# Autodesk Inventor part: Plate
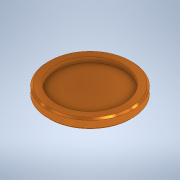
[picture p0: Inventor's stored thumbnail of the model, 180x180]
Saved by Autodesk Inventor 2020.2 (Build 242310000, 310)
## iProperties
Created: 2020-01
Part Number: Plate
Material: Gold
Document SubType Name: Modeling
Designer: thira
Density: 19.3 g/cm^3
Appearance: Metal 1600F Hot
Author: thira
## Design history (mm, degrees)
sketch "Sketch1"
  geometry: C1 r 125 at (0, 0); C2 r 100 at (0, 0); 1 further point
  constraints: 2 centre point, 2 coincident
  dimensions: "d0" = 250 diameter of C1; "d1" = 200 diameter of C2
extrude "Extrusion1" new body sketch "Sketch1" distance "d2" = 30; taper "d3" = 0 deg
extrude "Extrusion2" join sketch "Sketch1" distance "d4" = 15; taper "d5" = 0 deg
chamfer "Chamfer1" distance "d6" = 5; stored, may be unused: second distance "d7" = 2, angle "d8" = 45 deg
body "Solid1"
